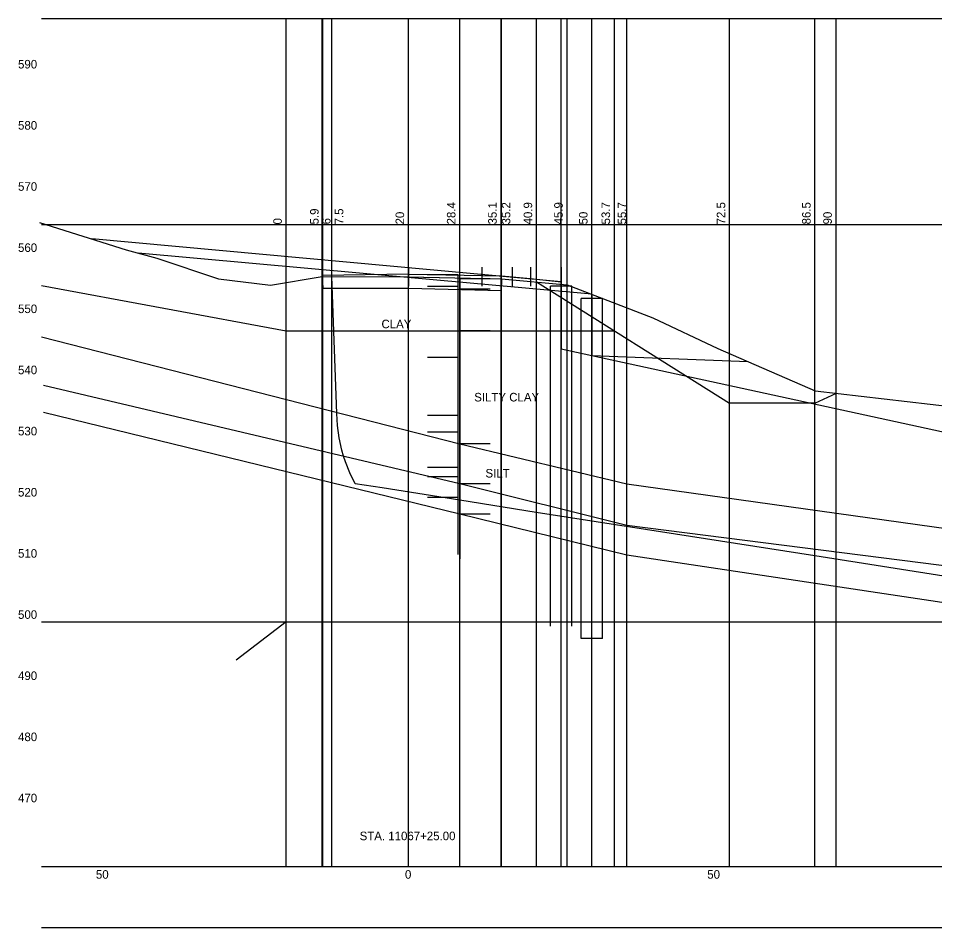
# Model space of a CAD drawing. Extents: x -64 to 1064, y -32 to 640.
# Drawn here: x -63.8 to 86.1, y 225.9 to 374.6 of the extents above; entities that cross this region are included whole.
import ezdxf

# ---------------------------------------------------------------- set-up
doc = ezdxf.new("R2010")
doc.units = 0
for name, color, linetype in [('DR_X_Headwall', 7, 'Continuous'), ('DR_X_Trench_Drain', 7, 'Continuous'), ('GT_Project_Soil_Boring', 7, 'Continuous'), ('GT_Project_Soil_Layers', 7, 'Continuous'), ('GT_X_Shear_Surface', 7, 'Continuous'), ('SC_Scratch1', 7, 'Continuous'), ('SH_Major_Grid_Line', 7, 'Continuous'), ('SH_Text', 7, 'Continuous')]:
    doc.layers.add(name, color=color, linetype=linetype)

msp = doc.modelspace()

# ---------------------------------------------------------------- linework, layer by layer
at = {"layer": 'DR_X_Headwall'}
for p, q in [((30, 329.46), (-44.2, 336.2)), ((23.25, 275.19), (23.25, 330.78)), ((26.75, 330.78), (23.25, 330.78)), ((26.75, 275.19), (26.75, 330.78)), ((28.25, 273.19), (28.25, 328.78)), ((31.75, 328.78), (28.25, 328.78)), ((31.75, 273.19), (31.75, 328.78)), ((31.75, 273.19), (28.25, 273.19))]:
    msp.add_line(p, q, dxfattribs=at)
for points in [[(25, 331.46), (25, 320.51), (207.39, 280.92)], [(30, 329.46), (30, 319.46), (55.57, 318.44)]]:
    msp.add_lwpolyline(points, dxfattribs=at)
at = {"layer": 'DR_X_Trench_Drain'}
for p, q in [((25, 331.51), (-51.8, 338.51)), ((0, 333.9), (0, 330.76)), ((12, 333.9), (12, 330.76)), ((17, 333.9), (17, 330.76)), ((20, 333.9), (20, 330.76)), ((25, 333.9), (25, 330.76)), ((0, 332.73), (-14.08, 332.51)), ((0, 332.73), (15.25, 332.49)), ((15.25, 332.49), (20, 332.01)), ((20, 332.01), (25, 331.51)), ((25, 331.11), (25, 320.51))]:
    msp.add_line(p, q, dxfattribs=at)
at = {"layer": 'GT_Project_Soil_Boring'}
for p, q in [((3.1, 332.68), (8.1, 332.68)), ((8.1, 332.68), (8.1, 286.88)), ((13.4, 331.98), (8.4, 331.98)), ((8.4, 331.98), (8.4, 286.21)), ((3.1, 330.78), (8.1, 330.78)), ((13.4, 330.28), (8.4, 330.28)), ((13.4, 323.48), (8.4, 323.48)), ((3.1, 319.18), (8.1, 319.18)), ((3.1, 309.68), (8.1, 309.68)), ((3.1, 306.98), (8.1, 306.98)), ((13.4, 304.98), (8.4, 304.98)), ((3.1, 301.18), (8.1, 301.18)), ((3.1, 299.68), (8.1, 299.68)), ((13.4, 298.48), (8.4, 298.48))]:
    msp.add_line(p, q, dxfattribs=at)
at = {"layer": 'GT_Project_Soil_Layers'}
for p, q in [((-14.08, 332.34), (-13.98, 330.44)), ((15.25, 331.98), (15.15, 330.08)), ((20.95, 331.47), (52.53, 311.66)), ((66.5, 311.66), (70, 313.27)), ((66.5, 311.66), (52.53, 311.66)), ((3.1, 296.28), (8.1, 296.28)), ((13.4, 293.48), (8.4, 293.48))]:
    msp.add_line(p, q, dxfattribs=at)
for points in [[(-14.08, 332.34), (0, 332.33), (15.25, 331.98)], [(-60, 330.88), (-20, 323.48), (33.69, 323.48)], [(-13.98, 330.44), (0, 330.43), (15.15, 330.08)], [(-60, 322.49), (8.4, 304.98), (35.75, 298.45), (215, 273.38)], [(215, 268.88), (35.75, 291.63), (8.4, 298.48), (-59.7, 314.56)], [(215, 259.88), (35.75, 286.78), (8.4, 293.48), (-59.7, 310.12)]]:
    msp.add_lwpolyline(points, dxfattribs=at)
at = {"layer": 'GT_X_Shear_Surface'}
msp.add_lwpolyline([(207.4, 280.98), (206.1, 274.68), (202.8, 268.58), (201.5, 267.08), (200.1, 265.68), (199, 265.78), (190, 267.28), (165.6, 271.08), (139.6, 275.18), (112.8, 279.38), (66.5, 286.68), (20.9, 293.78), (8.4, 295.78), (-4.3, 297.78), (-8.7, 298.48), (-9.6, 300.28), (-10.3, 302.08), (-10.6, 302.98), (-10.9, 303.98), (-11.3, 305.98), (-11.6, 307.98), (-11.7, 309.98), (-12.51, 332.34)], dxfattribs=at)
at = {"layer": 'SC_Scratch1'}
msp.add_line((-20, 275.88), (-28.17, 269.62), dxfattribs=at)
msp.add_lwpolyline([(-60.34, 341.22), (-46.19, 336.74), (-41.14, 335.38), (-31.04, 331.96), (-22.54, 330.96), (-14.08, 332.34), (-0.1, 332.33), (15.25, 331.98), (25.95, 331.02), (39.97, 325.62), (50.63, 320.59), (66.55, 313.64), (122.96, 307.11)], dxfattribs=at)
at = {"layer": 'SH_Major_Grid_Line'}
for p, q in [((-60, 374.58), (340, 374.58)), ((-20, 235.88), (-20, 374.58)), ((-14.08, 235.88), (-14.08, 374.58)), ((-13.98, 235.88), (-13.98, 374.58)), ((-12.51, 235.88), (-12.51, 374.58)), ((0, 235.88), (0, 374.58)), ((8.4, 235.88), (8.4, 374.58)), ((15.15, 235.88), (15.15, 374.58)), ((15.25, 235.88), (15.25, 374.58)), ((20.95, 235.88), (20.95, 374.58)), ((25, 235.88), (25, 374.58)), ((25.95, 235.88), (25.95, 374.58)), ((30, 235.88), (30, 374.58)), ((33.69, 235.88), (33.69, 374.58)), ((35.75, 235.88), (35.75, 374.58)), ((52.53, 235.88), (52.53, 374.58)), ((66.5, 235.88), (66.5, 374.58)), ((69.96, 235.88), (69.96, 374.58)), ((-60, 340.88), (280, 340.88)), ((-60, 275.88), (340, 275.88)), ((-60, 235.88), (340, 235.88)), ((-60, 225.88), (280, 225.88))]:
    msp.add_line(p, q, dxfattribs=at)

# ---------------------------------------------------------------- texts
at = {"layer": 'GT_Project_Soil_Boring'}
for s, p in [('CLAY', (-4.4, 323.9)), ('SILTY CLAY', (10.77, 311.93)), ('SILT', (12.61, 299.49))]:
    msp.add_text(s, height=1.4, dxfattribs=at).set_placement(p)
at = {"layer": 'GT_Project_Soil_Layers'}
for s, p in [('5.9', (-14.68, 340.88)), ('7.5', (-10.64, 340.88)), ('28.4', (7.7, 340.88)), ('35.1', (14.45, 340.88)), ('35.2', (16.67, 340.88)), ('40.9', (20.25, 340.88)), ('45.9', (25.25, 340.88)), ('53.7', (32.99, 340.88)), ('55.7', (35.62, 340.88)), ('72.5', (51.83, 340.88)), ('86.5', (65.8, 340.88)), ('0', (-20.7, 340.88)), ('6', (-12.74, 340.88)), ('20', (-0.7, 340.88)), ('50', (29.3, 340.88)), ('90', (69.26, 340.88))]:
    msp.add_text(s, height=1.4, rotation=90, dxfattribs=at).set_placement(p)
at = {"layer": 'SH_Text'}
for s, p in [('590', (-63.85, 366.38)), ('580', (-63.85, 356.38)), ('570', (-63.85, 346.38)), ('560', (-63.85, 336.38)), ('550', (-63.85, 326.38)), ('540', (-63.85, 316.38)), ('530', (-63.85, 306.38)), ('520', (-63.85, 296.38)), ('510', (-63.85, 286.38)), ('500', (-63.85, 276.38)), ('490', (-63.85, 266.38)), ('480', (-63.85, 256.38)), ('470', (-63.85, 246.38)), ('STA. 11067+25.00', (-7.97, 240.18)), ('50', (-51.11, 233.88)), ('0', (-0.56, 233.88)), ('50', (48.89, 233.88))]:
    msp.add_text(s, height=1.4, dxfattribs=at).set_placement(p)

doc.saveas('drawing.dxf')
